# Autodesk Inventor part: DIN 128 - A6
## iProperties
Created: 2008-08
Part Number: DIN 128 - A6
Material: BgAAAEgAAABOAEEATQBFAFMACgBNAGEAdABlAHIAaQBhAGwAcwAKADEAOgBTAHQAZQBlAGwALAAgAE0AaQBsAGQACgAKAEUATgBEAAoAAAA=
Description: Federring
Vendor: Autodesk Inc.
Document SubType Name: Modeling
Standard: DIN 128
Designer: U.Rapp
Standards Organization: DIN
Language: de-DE
Size Designation: A6
Categories: <MemberInstance Version="R10.0.0"><Categories><Category DisplayName="Schrauben" InternalName="e4da775c-781d-43d5-af7c-5136215cf5a6" Mnemonic="FSTN"><Category Di
Author: U.Rapp
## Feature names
1. Körper [Extrusion]
2. Schnitt [Extrusion]
